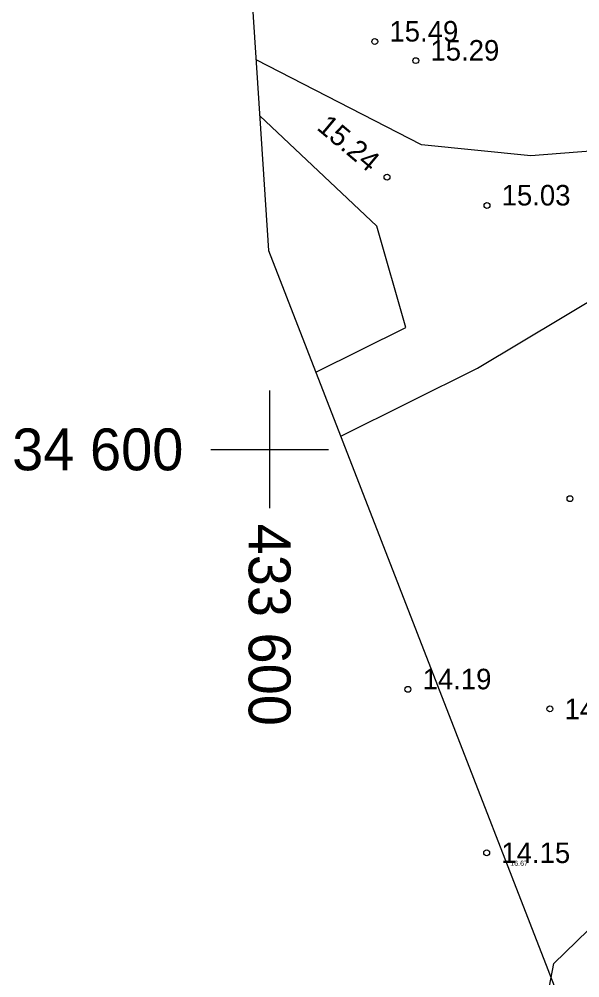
# Model space of a CAD drawing. Extents: x 433497 to 434382, y 6534486 to 6534993.
# Drawn here: x 433583 to 433621.1, y 6534564 to 6534629.3 of the extents above; entities that cross this region are included whole.
import ezdxf

# ---------------------------------------------------------------- set-up
doc = ezdxf.new("R2010")
doc.units = 0
for name, color, linetype in [('KORGUS-EH2000', 7, 'Continuous'), ('MOOTKORG-EH2000', 7, 'Continuous'), ('RELJEEF', 7, 'Continuous'), ('TEE', 7, 'Continuous'), ('VORK', 7, 'Continuous'), ('VORMISTUS', 7, 'Continuous')]:
    doc.layers.add(name, color=color, linetype=linetype)

msp = doc.modelspace()

# ---------------------------------------------------------------- linework, layer by layer
at = {"layer": 'KORGUS-EH2000'}
for centre in [(433607.158, 6534627.78), (433609.951, 6534626.482), (433607.993, 6534618.544), (433614.798, 6534616.613), (433620.448, 6534596.641), (433609.416, 6534583.656), (433619.081, 6534582.322), (433614.779, 6534572.521)]:
    msp.add_circle(centre, 0.2, dxfattribs=at)
at = {"layer": 'RELJEEF'}
msp.add_lwpolyline([(433633.604, 6534570.899), (433635.142, 6534568.685), (433635.8, 6534564.14), (433637.674, 6534561.797), (433636.499, 6534556.582), (433635.036, 6534555.26), (433631.846, 6534556.526), (433628.214, 6534553.782), (433623.313, 6534552.926), (433620.994, 6534556.892), (433618.633, 6534561.198), (433619.351, 6534564.99), (433622.457, 6534568.003), (433626.001, 6534569.994), (433629.936, 6534570.508), (433633.604, 6534570.899)], dxfattribs=at)
at = {"layer": 'TEE'}
for points in [[(433604.844, 6534600.897), (433614.152, 6534605.53), (433628.909, 6534614.355), (433639.149, 6534622.663), (433651.948, 6534640.714), (433661.037, 6534656.993), (433672.77, 6534669.323), (433685.557, 6534677.639), (433700.561, 6534685.076), (433716.344, 6534694.6), (433728.716, 6534707.321), (433752.812, 6534739.453), (433775.036, 6534762.988), (433798.049, 6534780.902), (433815.08, 6534789.81), (433832.403, 6534797.909), (433848.041, 6534804.286)], [(433629.62, 6534620.933), (433617.794, 6534619.989), (433610.334, 6534620.741), (433599.077, 6534626.526)], [(433609.28, 6534608.311), (433607.289, 6534615.198), (433599.327, 6534622.729)], [(433603.151, 6534605.26), (433609.28, 6534608.311)]]:
    msp.add_lwpolyline(points, dxfattribs=at)
at = {"layer": 'VORK'}
for p, q in [((433600, 6534604), (433600, 6534596)), ((433596, 6534600), (433604, 6534600))]:
    msp.add_line(p, q, dxfattribs=at)
at = {"layer": 'VORMISTUS'}
msp.add_lwpolyline([(433756.833, 6534894.348), (433691.203, 6534872.087), (433653.508, 6534864.187), (433636.546, 6534862.392), (433627.673, 6534847.824), (433564.128, 6534829.695), (433582.608, 6534768.478), (433587.883, 6534751.004), (433591.763, 6534747.472), (433594.096, 6534737.418), (433589.968, 6534732.121), (433592.57, 6534706.447), (433596.133, 6534671.303), (433599.93, 6534613.558), (433630.448, 6534534.937), (433664.149, 6534549.227), (433704.536, 6534572.568), (433752.081, 6534596.222), (433789.501, 6534614.839)], dxfattribs=at)
msp.add_lwpolyline([(433756.833, 6534894.348), (433691.203, 6534872.087), (433653.508, 6534864.187), (433636.546, 6534862.392), (433627.673, 6534847.824), (433564.128, 6534829.695), (433582.608, 6534768.478), (433587.883, 6534751.004), (433591.763, 6534747.472), (433594.096, 6534737.418), (433589.968, 6534732.121), (433592.57, 6534706.447), (433596.133, 6534671.303), (433599.93, 6534613.558), (433630.448, 6534534.937), (433664.149, 6534549.227), (433704.536, 6534572.568), (433752.081, 6534596.222), (433789.501, 6534614.839)], dxfattribs=at)

# ---------------------------------------------------------------- texts
at = {"layer": 'KORGUS-EH2000'}
for s, p in [('15.49', (433608.158, 6534627.78)), ('15.29', (433610.951, 6534626.482)), ('15.03', (433615.798, 6534616.613)), ('14.19', (433610.416, 6534583.656)), ('14.45', (433620.081, 6534581.622)), ('14.15', (433615.779, 6534571.821))]:
    msp.add_text(s, height=1.4, dxfattribs=at).set_placement(p)
msp.add_text('15.24', height=1.4, rotation=320.04259, dxfattribs=at).set_placement((433603.145, 6534621.834))
at = {"layer": 'MOOTKORG-EH2000'}
msp.add_text('16.67', height=0.35, dxfattribs=at).set_placement((433616.382, 6534571.632))
msp.add_text('16.67', height=0.35, dxfattribs=at).set_placement((433616.382, 6534571.632))
at = {"layer": 'VORK'}
msp.add_text('6 534 600 ', height=2.85, dxfattribs=at).set_placement((433577.174, 6534598.575))
msp.add_text(' 433 600', height=2.85, rotation=270, dxfattribs=at).set_placement((433598.575, 6534596))

doc.saveas('drawing.dxf')
